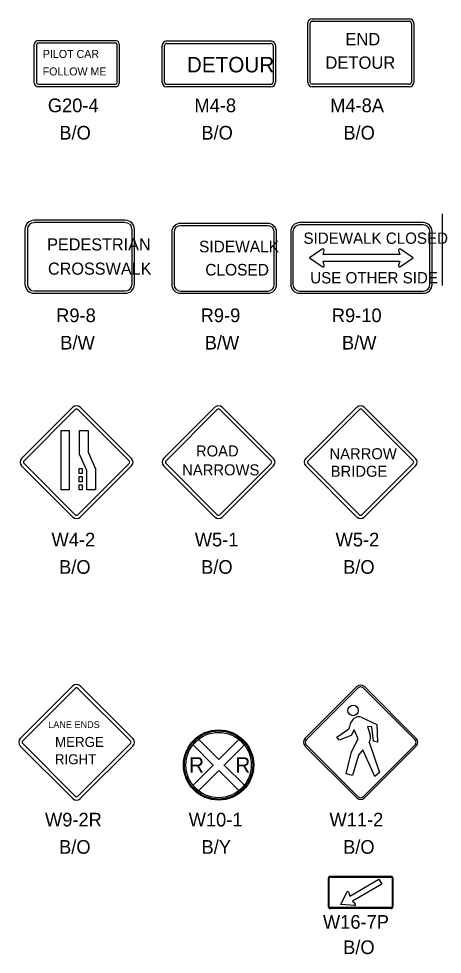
# Model space of a CAD drawing. Extents: x 10000 to 10794, y 10000 to 10499.
# Drawn here: x 10180 to 10288.5, y 10253.8 to 10493.6 of the extents above; entities that cross this region are included whole.
import ezdxf

# ---------------------------------------------------------------- set-up
doc = ezdxf.new("R2010")
doc.units = 0
for name, color, linetype in [('DSDate', 7, 'Continuous'), ('DSIndex', 7, 'Continuous'), ('DSText', 7, 'Continuous'), ('DSTitle', 7, 'Continuous'), ('PlotBorder_dp', 7, 'Continuous')]:
    doc.layers.add(name, color=color, linetype=linetype)

msp = doc.modelspace()

# ---------------------------------------------------------------- linework, layer by layer
at = {"layer": 'DSDate'}
for p, q in [((10254.67, 10489.62), (10254.67, 10492.39)), ((10255.24, 10492.96), (10280.02, 10492.96)), ((10280.58, 10492.39), (10280.58, 10489.47)), ((10254.67, 10477.23), (10254.67, 10489.67)), ((10280.58, 10489.67), (10280.58, 10477.34)), ((10184.58, 10477.09), (10184.58, 10487.05)), ((10184.94, 10487.37), (10204.74, 10487.37)), ((10205.1, 10487.05), (10205.1, 10477.09)), ((10217.33, 10477.34), (10217.33, 10486.69)), ((10217.89, 10487.26), (10244.57, 10487.26)), ((10245.14, 10486.69), (10245.14, 10477.34)), ((10204.74, 10476.77), (10184.94, 10476.77)), ((10244.57, 10476.77), (10217.89, 10476.77)), ((10280.02, 10476.78), (10255.12, 10476.78))]:
    msp.add_line(p, q, dxfattribs=at)
for points in [[(10207.27, 10441.33), (10183.9, 10441.33)], [(10182.17, 10439.59), (10182.17, 10425.57)], [(10209.01, 10425.57), (10209.01, 10439.59)], [(10219.76, 10438.88), (10219.76, 10425.46)], [(10243.77, 10440.54), (10221.42, 10440.54)], [(10245.43, 10425.46), (10245.43, 10438.88)], [(10183.9, 10423.83), (10207.27, 10423.83)], [(10221.42, 10423.81), (10243.77, 10423.81)]]:
    msp.add_lwpolyline(points, dxfattribs=at)
for centre, radius, start, end in [((10255.23, 10492.4), 0.566, 90, 180), ((10280.02, 10492.4), 0.566, 0, 90), ((10217.89, 10486.69), 0.566, 90, 180), ((10244.57, 10486.69), 0.566, 0, 90), ((10217.89, 10477.34), 0.566, 180, 270), ((10244.57, 10477.34), 0.566, 270, 0), ((10255.12, 10477.23), 0.453, 180, 270), ((10280.02, 10477.35), 0.566, 270, 0), ((10183.9, 10439.59), 1.73, 90, 180), ((10207.27, 10439.59), 1.73, 0, 90), ((10221.42, 10438.88), 1.66, 90, 180), ((10243.77, 10438.88), 1.66, 0, 90), ((10183.9, 10425.57), 1.73, 180, 270), ((10207.27, 10425.57), 1.73, 270, 0), ((10221.42, 10425.47), 1.66, 180, 270), ((10243.77, 10425.47), 1.66, 270, 0)]:
    msp.add_arc(centre, radius, start, end, dxfattribs=at)
for centre, major_axis, start_param, end_param in [((10184.94, 10487.05), (-0.359, 0), 4.712389, 6.283185), ((10204.74, 10487.05), (-0.359, 0), 3.141593, 4.712389), ((10184.94, 10477.09), (-0.359, 0), 0, 1.570796), ((10204.74, 10477.09), (0.359, 0), 4.712389, 6.283185)]:
    msp.add_ellipse(centre, major_axis=major_axis, ratio=0.888888, start_param=start_param, end_param=end_param, dxfattribs=at)
at = {"layer": 'DSIndex'}
for p, q in [((10283.61, 10441.34), (10251.92, 10441.34)), ((10283.61, 10440.77), (10251.92, 10440.77)), ((10249.66, 10439.07), (10249.66, 10425.49)), ((10250.22, 10439.07), (10250.22, 10425.49)), ((10285.3, 10425.49), (10285.3, 10439.07)), ((10285.87, 10425.49), (10285.87, 10439.07)), ((10257.72, 10434.5), (10254.47, 10432.28)), ((10257.93, 10433.13), (10258.24, 10434.17)), ((10277.29, 10434.17), (10277.59, 10433.13)), ((10281.06, 10432.28), (10277.81, 10434.5)), ((10254.47, 10432.28), (10257.72, 10430.07)), ((10277.59, 10433.13), (10257.93, 10433.13)), ((10258.24, 10430.39), (10257.93, 10431.43)), ((10257.93, 10431.43), (10277.59, 10431.43)), ((10277.59, 10431.43), (10277.29, 10430.39)), ((10277.81, 10430.07), (10281.06, 10432.28)), ((10251.92, 10423.8), (10283.61, 10423.8)), ((10251.92, 10423.23), (10283.61, 10423.23)), ((10180.7, 10380.87), (10193.85, 10394.02)), ((10181.31, 10380.28), (10194.44, 10393.41)), ((10195.12, 10393.41), (10208.25, 10380.28)), ((10195.72, 10394.02), (10208.86, 10380.87)), ((10193.85, 10365.86), (10180.7, 10379.01)), ((10194.44, 10366.47), (10181.31, 10379.6)), ((10208.25, 10379.6), (10195.12, 10366.47)), ((10208.86, 10379.01), (10195.72, 10365.86)), ((10266.62, 10322.44), (10253.3, 10309.13)), ((10266.93, 10322.12), (10253.62, 10308.81)), ((10281.51, 10308.81), (10268.2, 10322.12)), ((10281.83, 10309.13), (10268.52, 10322.44)), ((10265.94, 10314.32), (10266.5, 10314.6)), ((10267.67, 10314.6), (10271.68, 10312.71)), ((10261.47, 10309.49), (10264.56, 10311.58)), ((10265.94, 10311.33), (10265.17, 10309.95)), ((10266.94, 10309.06), (10265.94, 10311.33)), ((10270.42, 10312.09), (10269.32, 10312.22)), ((10269.32, 10312.22), (10269.95, 10310.34)), ((10270.89, 10308.42), (10270.42, 10312.09)), ((10271.68, 10312.71), (10271.92, 10308.18)), ((10231.19, 10303.76), (10226.01, 10308.94)), ((10231.19, 10303.76), (10236.35, 10308.92)), ((10262.08, 10308.68), (10261.47, 10309.49)), ((10265.17, 10309.95), (10262.08, 10308.68)), ((10265.24, 10305.71), (10266.94, 10309.06)), ((10229.78, 10302.34), (10224.61, 10307.51)), ((10232.6, 10302.34), (10237.78, 10307.52)), ((10253.3, 10307.22), (10266.62, 10293.91)), ((10253.62, 10307.54), (10266.93, 10294.23)), ((10268.2, 10294.23), (10281.51, 10307.54)), ((10268.52, 10293.91), (10281.83, 10307.22)), ((10271.92, 10308.18), (10270.89, 10308.42)), ((10263.88, 10300.09), (10265.24, 10305.71)), ((10266.98, 10304.9), (10265.52, 10299.64)), ((10268.16, 10306.27), (10266.98, 10304.9)), ((10271.22, 10299.39), (10268.16, 10306.27)), ((10224.62, 10297.18), (10229.78, 10302.34)), ((10231.19, 10302.34), (10231.23, 10302.34)), ((10237.77, 10297.18), (10232.6, 10302.34)), ((10232.61, 10302.35), (10232.62, 10302.36)), ((10225.98, 10295.72), (10231.19, 10300.93)), ((10236.33, 10295.79), (10231.19, 10300.93)), ((10265.52, 10299.64), (10263.88, 10300.09)), ((10264.76, 10268.78), (10272.24, 10273.1)), ((10272.24, 10273.1), (10273, 10271.8)), ((10273, 10271.8), (10265.51, 10267.48)), ((10262.51, 10266.61), (10264.01, 10269.74)), ((10264.55, 10269.68), (10264.76, 10268.78)), ((10265.97, 10266.34), (10262.51, 10266.61)), ((10265.51, 10267.48), (10266.19, 10266.84))]:
    msp.add_line(p, q, dxfattribs=at)
for points in [[(10288.48, 10443.58), (10288.48, 10425.21)], [(10269.74, 10308.18), (10272.42, 10300.41), (10271.22, 10299.39)], [(10259.29, 10266.08), (10259.29, 10273.32)], [(10259.52, 10266.08), (10259.52, 10273.32)], [(10259.8, 10273.84), (10275.33, 10273.84)], [(10259.8, 10273.6), (10275.33, 10273.6)], [(10275.61, 10273.32), (10275.61, 10266.08)], [(10275.85, 10273.32), (10275.85, 10266.08)], [(10275.33, 10265.8), (10259.8, 10265.8)], [(10275.33, 10265.56), (10259.8, 10265.56)]]:
    msp.add_lwpolyline(points, dxfattribs=at)
for points in [[(10190.8, 10388.06), (10192.85, 10388.06), (10192.85, 10372.88), (10190.8, 10372.88)], [(10195.56, 10388.06), (10197.75, 10388.06), (10197.75, 10382.54), (10199.64, 10378.25), (10199.64, 10372.88), (10197.37, 10372.88), (10197.37, 10377.79), (10195.56, 10381.99)], [(10195.45, 10378.36), (10196.22, 10378.36), (10196.22, 10377.06), (10195.45, 10377.06)], [(10195.45, 10376.25), (10196.22, 10376.25), (10196.22, 10374.95), (10195.45, 10374.95)], [(10195.45, 10374.18), (10196.22, 10374.18), (10196.22, 10372.88), (10195.45, 10372.88)], [(10224.62, 10297.18), (10224.66, 10297.07), (10224.79, 10296.92), (10224.96, 10296.74), (10225.06, 10296.59), (10225.27, 10296.41), (10225.44, 10296.22), (10225.63, 10296.03), (10225.82, 10295.9), (10225.98, 10295.72), (10231.19, 10300.93), (10236.33, 10295.79), (10236.53, 10295.91), (10236.78, 10296.14), (10237.04, 10296.35), (10237.26, 10296.62), (10237.54, 10296.86), (10237.77, 10297.18), (10232.6, 10302.34), (10237.78, 10307.52), (10237.55, 10307.7), (10237.42, 10307.92), (10237.21, 10308.16), (10237.02, 10308.37), (10236.78, 10308.56), (10236.6, 10308.73), (10236.35, 10308.92), (10231.19, 10303.76), (10226.01, 10308.94), (10225.82, 10308.73), (10225.55, 10308.53), (10225.25, 10308.27), (10224.99, 10307.96), (10224.72, 10307.68), (10224.61, 10307.51), (10229.78, 10302.34)]]:
    msp.add_lwpolyline(points, close=True, dxfattribs=at)
for centre, radius in [((10265.63, 10316.33), 1.34), ((10231.17, 10302.35), 9), ((10231.17, 10302.35), 8.75), ((10231.17, 10302.35), 8.37)]:
    msp.add_circle(centre, radius, dxfattribs=at)
for centre, radius, start, end in [((10251.92, 10439.07), 2.26, 90, 180), ((10251.92, 10439.07), 1.7, 90, 180), ((10283.61, 10439.07), 2.26, 0, 90), ((10283.61, 10439.07), 1.7, 0, 90), ((10257.93, 10434.26), 0.318, 343.6989, 132.4092), ((10277.6, 10434.26), 0.318, 47.5908, 196.3011), ((10257.93, 10430.3), 0.318, 227.5908, 16.3011), ((10277.6, 10430.3), 0.318, 163.6989, 312.4092), ((10251.92, 10425.49), 2.26, 180, 270), ((10251.92, 10425.49), 1.7, 180, 270), ((10283.61, 10425.49), 2.26, 270, 0), ((10283.61, 10425.49), 1.7, 270, 0), ((10194.78, 10393.08), 1.32, 45, 135), ((10194.78, 10393.07), 0.478, 45, 135), ((10181.64, 10379.94), 1.32, 135, 225), ((10207.92, 10379.94), 1.32, 315, 45), ((10181.65, 10379.94), 0.478, 135, 225), ((10207.91, 10379.94), 0.478, 315, 45), ((10194.78, 10366.81), 0.478, 225, 315), ((10194.78, 10366.8), 1.32, 225, 315), ((10267.57, 10321.49), 1.34, 45, 135), ((10267.57, 10321.49), 0.896, 45, 135), ((10269.89, 10310.85), 5.38, 143.7968, 172.2325), ((10266.53, 10313.11), 1.34, 116.1532, 136.9703), ((10267.1, 10313.39), 1.34, 64.7035, 116.1532), ((10254.26, 10308.18), 1.34, 135, 225), ((10254.26, 10308.18), 0.896, 135, 225), ((10267.4, 10309.49), 2.69, 330.8347, 18.4267), ((10280.88, 10308.18), 0.896, 315, 45), ((10280.88, 10308.18), 1.34, 315, 45), ((10267.57, 10294.86), 1.34, 225, 315), ((10267.57, 10294.86), 0.896, 225, 315), ((10259.8, 10273.32), 0.518, 90, 180), ((10259.8, 10273.32), 0.28, 90, 180), ((10275.33, 10273.32), 0.518, 0, 90), ((10275.33, 10273.32), 0.28, 0, 90), ((10264.27, 10269.62), 0.288, 13.3557, 154.4881), ((10259.8, 10266.08), 0.518, 180, 270), ((10259.8, 10266.08), 0.28, 180, 270), ((10265.99, 10266.63), 0.288, 265.5119, 46.6443), ((10275.33, 10266.08), 0.518, 270, 360), ((10275.33, 10266.08), 0.28, 270, 360)]:
    msp.add_arc(centre, radius, start, end, dxfattribs=at)
at = {"layer": 'DSText'}
for p, q in [((10255.12, 10493.59), (10280.02, 10493.59)), ((10254.04, 10489.59), (10254.04, 10492.51)), ((10281.21, 10492.39), (10281.21, 10489.55)), ((10254.04, 10477.23), (10254.04, 10489.67)), ((10281.21, 10489.67), (10281.21, 10477.34)), ((10183.95, 10477.09), (10183.95, 10487.05)), ((10184.94, 10487.99), (10204.74, 10487.99)), ((10205.73, 10487.05), (10205.73, 10477.09)), ((10216.7, 10477.34), (10216.7, 10486.69)), ((10217.89, 10487.89), (10244.57, 10487.89)), ((10245.76, 10486.69), (10245.76, 10477.34)), ((10204.74, 10476.15), (10184.94, 10476.15)), ((10244.57, 10476.15), (10217.89, 10476.15)), ((10280.02, 10476.15), (10255.12, 10476.15)), ((10217.09, 10380.87), (10230.24, 10394.02)), ((10232.11, 10394.02), (10245.26, 10380.87)), ((10253.49, 10380.87), (10266.63, 10394.02)), ((10268.5, 10394.02), (10281.65, 10380.87)), ((10230.24, 10365.86), (10217.09, 10379.01)), ((10245.26, 10379.01), (10232.11, 10365.86)), ((10266.63, 10365.86), (10253.49, 10379.01)), ((10281.65, 10379.01), (10268.5, 10365.86)), ((10180.35, 10309.13), (10193.83, 10322.61)), ((10195.74, 10322.61), (10209.22, 10309.13)), ((10193.83, 10293.74), (10180.35, 10307.22)), ((10209.22, 10307.22), (10195.74, 10293.74))]:
    msp.add_line(p, q, dxfattribs=at)
for points in [[(10207.27, 10441.93), (10183.9, 10441.93)], [(10243.77, 10441.11), (10221.42, 10441.11)], [(10181.56, 10439.59), (10181.56, 10425.57)], [(10209.61, 10425.57), (10209.61, 10439.59)], [(10219.18, 10438.88), (10219.18, 10425.46)], [(10246, 10425.46), (10246, 10438.88)], [(10183.9, 10423.23), (10207.27, 10423.23)], [(10221.42, 10423.23), (10243.77, 10423.23)]]:
    msp.add_lwpolyline(points, dxfattribs=at)
for centre, radius, start, end in [((10255.12, 10492.51), 1.08, 90, 180), ((10280.02, 10492.4), 1.19, 0, 90), ((10217.89, 10486.69), 1.19, 90, 180), ((10217.89, 10486.69), 0.566, 90, 180), ((10244.57, 10486.69), 1.19, 0, 90), ((10217.89, 10477.34), 1.19, 180, 270), ((10244.57, 10477.34), 1.19, 270, 0), ((10255.12, 10477.23), 1.08, 180, 270), ((10280.02, 10477.34), 1.19, 270, 0), ((10183.9, 10439.59), 2.34, 90, 180), ((10207.27, 10439.59), 2.34, 0, 90), ((10221.42, 10438.88), 2.24, 90, 180), ((10243.77, 10438.88), 2.24, 0, 90), ((10183.9, 10425.57), 2.34, 180, 270), ((10207.27, 10425.57), 2.34, 270, 0), ((10221.42, 10425.47), 2.24, 180, 270), ((10243.77, 10425.47), 2.24, 270, 0), ((10231.17, 10393.08), 1.32, 45, 135), ((10267.57, 10393.08), 1.32, 45, 135), ((10218.03, 10379.94), 1.32, 135, 225), ((10244.31, 10379.94), 1.32, 315, 45), ((10254.43, 10379.94), 1.32, 135, 225), ((10280.71, 10379.94), 1.32, 315, 45), ((10231.18, 10366.8), 1.32, 225, 315), ((10267.57, 10366.8), 1.32, 225, 315), ((10194.78, 10321.65), 1.36, 45, 135), ((10181.31, 10308.17), 1.36, 135, 225), ((10208.25, 10308.18), 1.36, 315, 45), ((10194.79, 10294.7), 1.36, 225, 315)]:
    msp.add_arc(centre, radius, start, end, dxfattribs=at)
for centre, major_axis, start_param, end_param in [((10184.94, 10487.05), (-0.984, 0), 4.712389, 6.283185), ((10204.74, 10487.05), (-0.984, 0), 3.141593, 4.712389), ((10184.94, 10477.09), (-0.984, 0), 0, 1.570796), ((10204.74, 10477.09), (0.984, 0), 4.712389, 6.283185)]:
    msp.add_ellipse(centre, major_axis=major_axis, ratio=0.959484, start_param=start_param, end_param=end_param, dxfattribs=at)
at = {"layer": 'DSTitle'}
for p, q in [((10217.71, 10380.28), (10230.84, 10393.41)), ((10231.52, 10393.41), (10244.64, 10380.28)), ((10254.1, 10380.28), (10267.23, 10393.41)), ((10267.91, 10393.41), (10281.04, 10380.28)), ((10230.84, 10366.47), (10217.71, 10379.6)), ((10244.64, 10379.6), (10231.52, 10366.47)), ((10267.23, 10366.47), (10254.1, 10379.6)), ((10281.04, 10379.6), (10267.91, 10366.47)), ((10180.98, 10308.52), (10194.44, 10321.98)), ((10195.13, 10321.98), (10208.59, 10308.52)), ((10194.44, 10294.37), (10180.98, 10307.83)), ((10208.59, 10307.83), (10195.13, 10294.37))]:
    msp.add_line(p, q, dxfattribs=at)
for centre, radius, start, end in [((10231.17, 10393.07), 0.478, 45, 135), ((10267.57, 10393.07), 0.478, 45, 135), ((10218.04, 10379.94), 0.478, 135, 225), ((10244.31, 10379.94), 0.478, 315, 45), ((10254.43, 10379.94), 0.478, 135, 225), ((10280.7, 10379.94), 0.478, 315, 45), ((10231.17, 10366.81), 0.478, 225, 315), ((10267.57, 10366.81), 0.478, 225, 315), ((10194.78, 10321.64), 0.49, 45, 135), ((10181.32, 10308.18), 0.49, 135, 225), ((10208.24, 10308.18), 0.49, 315, 45), ((10194.78, 10294.72), 0.49, 225, 315)]:
    msp.add_arc(centre, radius, start, end, dxfattribs=at)

# ---------------------------------------------------------------- texts
at = {"layer": 'DSIndex'}
for s, height, p in [('SIDEWALK CLOSED', 2.8971, (10252.92, 10435.9)), ('USE OTHER SIDE', 2.8971, (10254.65, 10425.76)), ('R9-10', 3.5, (10260.19, 10415.83)), ('B/W', 3.5, (10262.78, 10408.82)), ('W4-2', 3.5, (10188.36, 10358.36)), ('B/O', 3.5, (10190.3, 10351.35)), ('R', 4, (10223.59, 10300.35)), ('R', 4, (10235.42, 10300.35)), ('W10-1', 3.5, (10223.5, 10286.6)), ('W11-2', 3.5, (10259.58, 10286.6)), ('B/Y', 3.5, (10226.8, 10279.61)), ('B/O', 3.5, (10263.08, 10279.61)), ('W16-7P', 3.5, (10257.91, 10260.4)), ('B/O', 3.5, (10263.08, 10253.9))]:
    msp.add_text(s, height=height, dxfattribs=at).set_placement(p)
at = {"layer": 'PlotBorder_dp'}
for s, height, p in [('END', 3.17, (10263.64, 10486.75)), ('PILOT CAR', 2.038, (10186.14, 10483.54)), ('DETOUR', 3.963, (10223.04, 10479.84)), ('DETOUR', 3.17, (10258.54, 10480.75)), ('FOLLOW ME', 2.038, (10186.08, 10479.05)), ('G20-4', 3.5, (10187.41, 10469.63)), ('M4-8', 3.5, (10224.98, 10469.63)), ('M4-8A', 3.5, (10259.76, 10469.63)), ('B/O', 3.5, (10190.36, 10462.62)), ('B/O', 3.5, (10226.75, 10462.62)), ('B/O', 3.5, (10263.14, 10462.62)), ('PEDESTRIAN', 3.104, (10187.24, 10434.2)), ('SIDEWALK', 2.968, (10226.15, 10433.72)), ('CROSSWALK', 3.104, (10187.45, 10427.99)), ('CLOSED', 2.968, (10227.75, 10427.78)), ('R9-8', 3.5, (10189.55, 10415.83)), ('R9-9', 3.5, (10226.58, 10415.83)), ('B/W', 3.5, (10190.6, 10408.82)), ('B/W', 3.5, (10227.61, 10408.82)), ('ROAD', 2.831, (10225.37, 10381.41)), ('NARROW', 2.831, (10259.58, 10380.7)), ('NARROWS', 2.831, (10221.84, 10376.57)), ('BRIDGE', 2.831, (10259.9, 10376.21)), ('W5-1', 3.5, (10225.07, 10358.36)), ('W5-2', 3.5, (10261.15, 10358.36)), ('B/O', 3.5, (10226.69, 10351.35)), ('B/O', 3.5, (10263.08, 10351.35)), ('LANE ENDS', 1.742, (10187.51, 10311.84)), ('MERGE', 2.553, (10189.26, 10306.99)), ('RIGHT', 2.553, (10189.21, 10302.54)), ('W9-2R', 3.5, (10186.69, 10286.6)), ('B/O', 3.5, (10190.3, 10279.61))]:
    msp.add_text(s, height=height, dxfattribs=at).set_placement(p)

doc.saveas('drawing.dxf')
